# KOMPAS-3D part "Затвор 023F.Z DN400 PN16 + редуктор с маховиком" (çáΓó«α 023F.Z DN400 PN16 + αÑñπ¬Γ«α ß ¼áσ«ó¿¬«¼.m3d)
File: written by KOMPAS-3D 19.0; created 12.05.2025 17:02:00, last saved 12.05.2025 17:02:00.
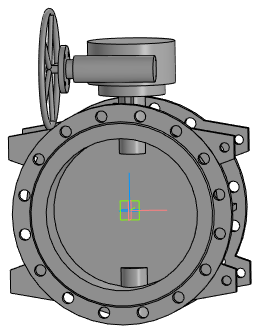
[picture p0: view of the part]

Document properties: Полное имя файла: Затвор 023F.Z DN400 PN16 + редуктор с маховиком.a3d

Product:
- Part/product: Затвор 023F.Z DN400 PN16 + редуктор с маховиком
    Масса: 200.439

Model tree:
1. Операция без истории:1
